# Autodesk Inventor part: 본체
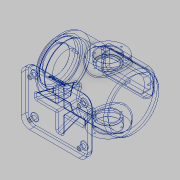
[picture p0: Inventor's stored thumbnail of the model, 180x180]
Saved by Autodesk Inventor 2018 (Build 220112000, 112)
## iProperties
Created: 2021-11
Part Number: 본체
Material: 알루미늄 6061
Document SubType Name: Modeling
Designer: home
Density: 2.7 g/cm^3
Appearance: 알루미늄 - 평지
Mass: 3539.16 g
Surface Area: 2411.25 cm^2
Volume: 1310.8 cm^3
Author: home
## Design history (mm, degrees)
sketch "스케치1"
  geometry: L1 (-117, 65)-(0, 65); L2 (0, 65)-(58.993, 65); L3 (0, 65)-(58.993, 65); L4 (-117, 47.5)-(-117, 65); L5 (-117, 0)-(83, 0); L6 (-21, 0)-(21, 0); L7 (-102, 55)-(54.239, 55); L8 (83, 0)-(-127, 0); L9 (-127, 32.5)-(-127, 47.5); L10 (-127, 47.5)-(-117, 47.5); L11 (-127, 0)-(-102, 0); L12 (-102, 32.5)-(-127, 32.5); L13 (-102, 32.5)-(-102, 55); A1 r 21 centre (0, 0) between (21, 0) and (-21, 0); A2 r 100 centre (-17, 0) between (83, 0) and (58.993, 65); A3 r 90 centre (-17, 0) between (73, 0) and (54.239, 55); 3 further points
  constraints: 26 end point, 6 point on circle, 4 horizontal, 3 centre point, 3 point on line, 2 perpendicular, 2 vertical, 1 coincident, 1 collinear, 1 parallel, 1 tangent
  dimensions: "d0" = 42 diameter of A1; "d11" = 100 radius of A2; "d12" = 83 distance of L5.end point (0, 0); "d16" = 65 distance between parallel lines of L6 L3; "d17" = 65 distance between parallel lines of L3 L5; "d18" = 65 distance from line of point (0, 0) L2; "d20" = 0 distance from line of point (83, 65) L2; "d21" = 200 distance from line of point (83, 65) L4; "d22" = 117 distance from line of L1.end L4; "d24" = 10 radial gap between concentric circles of A2 A3; "d29" = 10 distance between parallel lines of L7 L3; "d30" = 32.5 distance between parallel lines of L12 L3; "d31" = 17.5 distance between parallel lines of L10 L3; "d206" = 25 distance of L12.start L9.start; "d207" = 15 distance between parallel lines of L13 L4; "d208" = 102 distance from line of point (0, 0) L13; "d209" = 0 distance from line of L11.end L13; "d210" = 5 distance from line of point (-107, 32.5) L13; "d211" = 15 distance from line of L5.start L13; "d212" = 25 distance from line of L8.end L13
revolve "회전1" sketch "스케치1" stored, may be unused: angle "d23" = 90 deg
node "작업 평면1"
sketch "스케치2"
  geometry: L1 (77, 15)-(77, -15); L2 (-43, 15)-(-43, -15); L3 (62, -30)-(-28, -30); L4 (62, 30)-(-28, 30); A1 r 15 centre (62, -15) between (62, -30) and (77, -15); A2 r 15 centre (62, 15) between (77, 15) and (62, 30); A3 r 15 centre (-28, 15) between (-28, 30) and (-43, 15); A4 r 15 centre (-28, -15) between (-43, -15) and (-28, -30); 1 further point
  constraints: 10 tangent, 8 end point, 8 point on circle, 4 centre point, 3 equal radius, 1 horizontal, 1 parallel, 1 vertical
  dimensions: "d39" = 120 distance between parallel lines of L1 L2; "d44" = 15 radius of A1; "d45" = 77 distance from line of point (0, 0) L1; "d46" = 30 distance from line of point (0, 0) L4
extrude "돌출1" join sketch "스케치2" stored distance "d47" = 10; taper "d48" = 0 deg
node "작업 평면2"
sketch "스케치3"
  geometry: C1 r 40 at (0, 0); 1 further point
  constraints: 1 centre point, 1 coincident
  dimensions: "d55" = 80 diameter of C1
extrude "돌출2" join sketch "스케치3" stored distance "d56" = 10; taper "d57" = 0 deg
hole "구멍1" diameter "d60" = 42; stored, may be unused: countersink angle "d64" = 90 deg, drill point angle "d66" = 0 deg; dims "d58" = 10, "d59" = 10, "d61" = 6, "d62" = 52, "d63" = 18, "d65" = 60
node "작업 평면3"
sketch "스케치5"
  geometry: L1 (97, 45)-(97, -45); L2 (-63, 45)-(-63, -45); L3 (77, -65)-(-43, -65); L4 (77, 65)-(-43, 65); A1 r 20 centre (77, -45) between (77, -65) and (97, -45); A2 r 20 centre (-43, -45) between (-63, -45) and (-43, -65); A3 r 20 centre (-43, 45) between (-43, 65) and (-63, 45); A4 r 20 centre (77, 45) between (97, 45) and (77, 65); 4 further points
  constraints: 8 end point, 8 point on circle, 8 tangent, 6 point on line, 4 centre point, 3 equal radius, 2 parallel, 1 horizontal, 1 vertical
  dimensions: "d73" = 160 distance of point (97, -65) point (-63, -65); "d74" = 130 distance of point (97, 65) point (97, -65); "d76" = 20 radius of A1; "d77" = 97 distance from line of point (0, 0) L1; "d78" = 65 distance from line of point (0, 0) L4
extrude "돌출3" join sketch "스케치5" distance "d79" = 14; taper "d80" = 0 deg
sketch "스케치7"
  geometry: L1 (43, -100)-(-77, -100) reference; L2 (43, -100)-(26.985, -56); L3 (-77, -100)-(-60.985, -56); L4 (-77, -100)-(-23.285, -100); L5 (-60.985, -56)-(26.985, -56); L6 (-77, -100)-(43, -100); 1 further point
  constraints: 10 end point, 1 collinear, 1 horizontal, 1 parallel
  dimensions: "d96" = 70 deg angle of L4 L3; "d97" = 70 deg angle of L2 L1; "d98" = 44 distance between parallel lines of L5 L1; "d99" = 62.28725 distance from line of L4.end L2
extrude "돌출5" join sketch "스케치7" stored distance "d100" = 14; taper "d101" = 0 deg
sketch "스케치9"
  geometry: L1 (40.41, 9.298)-(81.889, 9.298); L2 (81.889, 9.298)-(81.889, 3.294); L3 (81.889, 3.294)-(40.41, 3.294); L4 (40.41, 3.294)-(40.41, 9.298); 1 further point
  constraints: 1 horizontal, 2 other
  dimensions: "d113" = 41.47897 distance between parallel lines of L4 L2; "d114" = 6.00407 distance between parallel lines of L1 L3; "d115" = 4.88899 distance from line of point (77, 114) L2; "d116" = 104.7016 distance from line of point (77, 114) L1
feature "엠보싱1" sketch "스케치9" dims "d0" = 42, "d11" = 100, "d12" = 83, "d16" = 65, "d17" = 65, "d18" = 65, "d20" = 0, "d21" = 200, "d22" = 117, "d24" = 10, "d29" = 10, "d30" = 32.5, "d31" = 17.5, "d117" = 0.5, "d118" = 0, "d206" = 25, "d207" = 15, "d208" = 102, "d209" = 0, "d210" = 5, "d211" = 15, "d212" = 25
sketch "스케치10"
  geometry: L1 (-77, -65)-(43, -65) reference; L2 (-97, 45)-(-97, -45) reference; L3 (43, 65)-(-77, 65) reference; L4 (63, -45)-(63, 45) reference; A1 r 20 centre (-77, 45) between (-77, 65) and (-97, 45) reference; A2 r 20 centre (-77, -45) between (-97, -45) and (-77, -65) reference; A3 r 20 centre (-77, 45) between (-77, 65) and (-97, 45) reference; A4 r 20 centre (43, 45) between (63, 45) and (43, 65) reference; A5 r 20 centre (43, -45) between (43, -65) and (63, -45) reference; A6 r 20 centre (-77, -45) between (-97, -45) and (-77, -65) reference; 4 further points
  constraints: 4 coincident
hole "구멍2" sketch "스케치10" at (-77, 45), (43, 45), (43, -45), (-77, -45) diameter "d129" = 9; stored, may be unused: countersink angle "d133" = 90 deg, drill point angle "d135" = 0 deg; dims "d130" = 6, "d131" = 18, "d132" = 2, "d134" = 14
node "작업 평면5"
sketch "스케치11"
  geometry: L1 (110, 0)-(110, 14) reference; L2 (-5, 14)-(12.476, 62.015); L3 (-5, 14)-(46.096, 14); 1 further point
  constraints: 4 end point, 1 equal length, 1 horizontal
  dimensions: "d138" = 70 deg angle of L3 L2; "d139" = 0 distance from line of L1.end L3; "d140" = 108.06465 distance from line of L1.end L2; "d141" = 63.90366 distance from line of L3.end L1
feature "리브2" sketch "스케치11" dims "d142" = 1, "d143" = 14, "d144" = 0, "d145" = 0, "d146" = 1, "d147" = 1
sketch "스케치12"
  geometry: 5 further points
  dimensions: "d149" = 32.5 distance of point (0, 0) point (32.5, 0); "d150" = 32.5 distance of point (0, 0) point (0, 32.5); "d151" = 32.5 distance of point (0, 0) point (0, -32.5); "d152" = 32.5 distance of point (0, 0) point (-32.5, 0); "d153" = 45.96194 distance of point (32.5, 0) point (0, 32.5); "d154" = 45.96194 distance of point (32.5, 0) point (0, -32.5); "d155" = 65 distance of point (32.5, 0) point (-32.5, 0); "d156" = 32.5 horizontal distance of point (32.5, 0) point (0, 32.5)
hole "구멍3" sketch "스케치12" at (0, 32.5), (-32.5, 0), (0, -32.5), (32.5, 0) diameter "d157" = 3.242; stored, may be unused: countersink angle "d161" = 90 deg, drill point angle "d163" = 118 deg; dims "d158" = 11, "d159" = 18, "d160" = 2, "d162" = 13
sketch "스케치13"
  geometry: 5 further points
  dimensions: "d165" = 40 distance of point (0, 0) point (40, 0); "d166" = 40 distance of point (0, 0) point (0, 40); "d167" = 40 distance of point (0, 0) point (0, -40); "d168" = 40 distance of point (0, 0) point (-40, 0); "d169" = 56.56854 distance of point (40, 0) point (0, 40); "d170" = 56.56854 distance of point (40, 0) point (0, -40); "d171" = 80 distance of point (40, 0) point (-40, 0); "d172" = 40 horizontal distance of point (40, 0) point (0, 40)
hole "구멍4" sketch "스케치13" at (0, 40), (40, 0), (0, -40), (-40, 0) diameter "d173" = 3.242; stored, may be unused: countersink angle "d177" = 90 deg, drill point angle "d179" = 118 deg; dims "d174" = 11, "d175" = 18, "d176" = 2, "d178" = 13
sketch "스케치14"
  geometry: L1 (28, 30)-(-62, 30) reference; L2 (-62, -30)-(28, -30) reference; L3 (43, -15)-(43, 15) reference; L4 (28, 30)-(-62, 30) reference; L5 (-77, 15)-(-77, -15) reference; L6 (33, 15)-(33, -15); L7 (28, -20)-(-62, -20); L8 (-67, -15)-(-67, 15); L9 (-62, 20)-(28, 20); A1 r 15 centre (28, -15) between (28, -30) and (43, -15) reference; A2 r 15 centre (28, 15) between (43, 15) and (28, 30) reference; A3 r 15 centre (-62, 15) between (-62, 30) and (-77, 15) reference; A4 r 15 centre (-62, -15) between (-77, -15) and (-62, -30) reference; A5 r 5 centre (28, -15) between (28, -20) and (33, -15); A6 r 5 centre (-62, -15) between (-67, -15) and (-62, -20); A7 r 5 centre (-62, 15) between (-62, 20) and (-67, 15); A8 r 5 centre (28, 15) between (33, 15) and (28, 20); 1 further point
  constraints: 8 end point, 8 point on circle, 4 centre point, 7 other
  dimensions: "d180" = 10 distance between parallel lines of L3 L6
extrude "돌출6" cut sketch "스케치14" distance "d181" = 50; taper "d182" = 0 deg
sketch "스케치15"
  geometry: L1 (33, 15)-(33, -15) reference; L2 (28, -20)-(-62, -20) reference; L3 (-67, -15)-(-67, 15) reference; L4 (-62, 20)-(28, 20) reference; L5 (-62, -30)-(28, -30) reference; L6 (43, -15)-(43, 15) reference; L7 (28, 30)-(-62, 30) reference; L8 (-77, 15)-(-77, -15) reference; A1 r 5 centre (28, 15) between (33, 15) and (28, 20) reference; A2 r 5 centre (28, -15) between (28, -20) and (33, -15) reference; A3 r 5 centre (-62, -15) between (-67, -15) and (-62, -20) reference; A4 r 5 centre (-62, 15) between (-62, 20) and (-67, 15) reference; A5 r 15 centre (28, -15) between (28, -30) and (43, -15) reference; A6 r 15 centre (28, 15) between (43, 15) and (28, 30) reference; A7 r 15 centre (-62, 15) between (-62, 30) and (-77, 15) reference; A8 r 15 centre (-62, -15) between (-77, -15) and (-62, -30) reference; 5 further points
  dimensions: "d184" = 5 distance from line of point (38, 0) L6; "d185" = 30 distance from line of point (38, 0) L7; "d186" = 60 distance from line of point (-17, 25) L6; "d187" = 5 distance from line of point (-17, 25) L7; "d188" = 60 distance from line of point (-17, -25) L6; "d189" = 55 distance from line of point (-17, -25) L7; "d190" = 115 distance from line of point (-72, 0) L6; "d191" = 30 distance from line of point (-72, 0) L7
hole "구멍5" sketch "스케치15" at (-17, 25), (-72, 0), (-17, -25), (38, 0) diameter "d192" = 3.242; stored, may be unused: countersink angle "d196" = 90 deg, drill point angle "d198" = 118 deg; dims "d193" = 9, "d194" = 18, "d195" = 2, "d197" = 11
chamfer "모따기1" distance "d199" = 1; stored, may be unused: second distance "d200" = 2, angle "d201" = 45 deg
fillet "모깎기1" dims "d202" = 0.3
fillet "모깎기2" dims "d203" = 3
fillet "모깎기3" dims "d204" = 3
fillet "모깎기4" dims "d205" = 10
fillet "모깎기5" dims "d213" = 3
node "솔리드1"
mirror "미러1"
mirror "미러3"
mirror "미러4"
node "투영된 루프2"
node "투영된 루프3"
node "투영된 루프4"
other parameters: "d49" = 75, "d67" = -114
